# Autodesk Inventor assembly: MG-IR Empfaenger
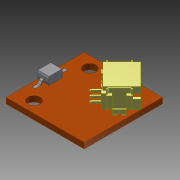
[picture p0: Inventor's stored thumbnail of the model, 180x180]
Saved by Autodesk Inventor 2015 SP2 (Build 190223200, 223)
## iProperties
Created: 2015-09
Part Number: MG-IR Empfaenger
Document SubType Name: Assembly
Designer: rYan
Author: rYan
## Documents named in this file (4)
- E:\Tigers SVN\mechanik\2016\Inventor\Elektronik\MG-IR Empfaenger.iam
- E:\Tigers SVN\mechanik\2016\Inventor\Elektronik\IR Board.ipt
- E:\Tigers SVN\mechanik\2016\Inventor\Kaufteile\IR LED Reverse Gullwing.ipt
- E:\Tigers SVN\mechanik\2016\Inventor\Kaufteile\DF13A-3P-1.25H.ipt
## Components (3 placed, 3 different names)
1. IR Board:1 — Einfügen:1, Winkel:1, Passend:2, Winkel:3
2. IR LED Reverse Gullwing:1 — Einfügen:1, Winkel:1
3. DF13A-3P-1.25H:1 — Passend:2, Winkel:3
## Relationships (4: Angle 2, Insert 1, Mate 1)
- Einfügen:1 [Insert]: IR Board:1 ↔ IR LED Reverse Gullwing:1
- Winkel:1 [Angle]: IR Board:1 ↔ IR LED Reverse Gullwing:1
- Passend:2 [Mate]: IR Board:1 ↔ DF13A-3P-1.25H:1
- Winkel:3 [Angle]: IR Board:1 ↔ DF13A-3P-1.25H:1
